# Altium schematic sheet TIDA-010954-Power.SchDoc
size 431 x 279 mm; Date: Not shown in title block; ApprovedBy: Not shown in title block; CheckedBy: Not shown in title block; Author: Not shown in title block; CompanyName: Not shown in title block; Engineer: Not shown in title block; Organization: Not shown in title block; Address1: Not shown in title block; Address2: Not shown in title block; Address3: Not shown in title block; Address4: Not shown in title block; DocumentNumber: 2; Revision: Use project parameter SCH_Rev; SheetNumber: 6; SheetTotal: 9; PageSetup: Record=PageOptions¦CenterHorizontal=True¦CenterVertical=True¦PrintScale=1.00¦XCorrection=1.00¦YCorrection=1.00¦PrintKind=0¦BorderSize=5000000¦LeftOffset=0¦BottomOffset=0¦Orientation=2¦PaperLength=1000¦PaperWidth=1000¦Scale=100¦PaperSource=15¦PrintQuality=600¦MediaType=1¦DitherType=10¦PaperKind=Letter¦PrintScaleMode=1
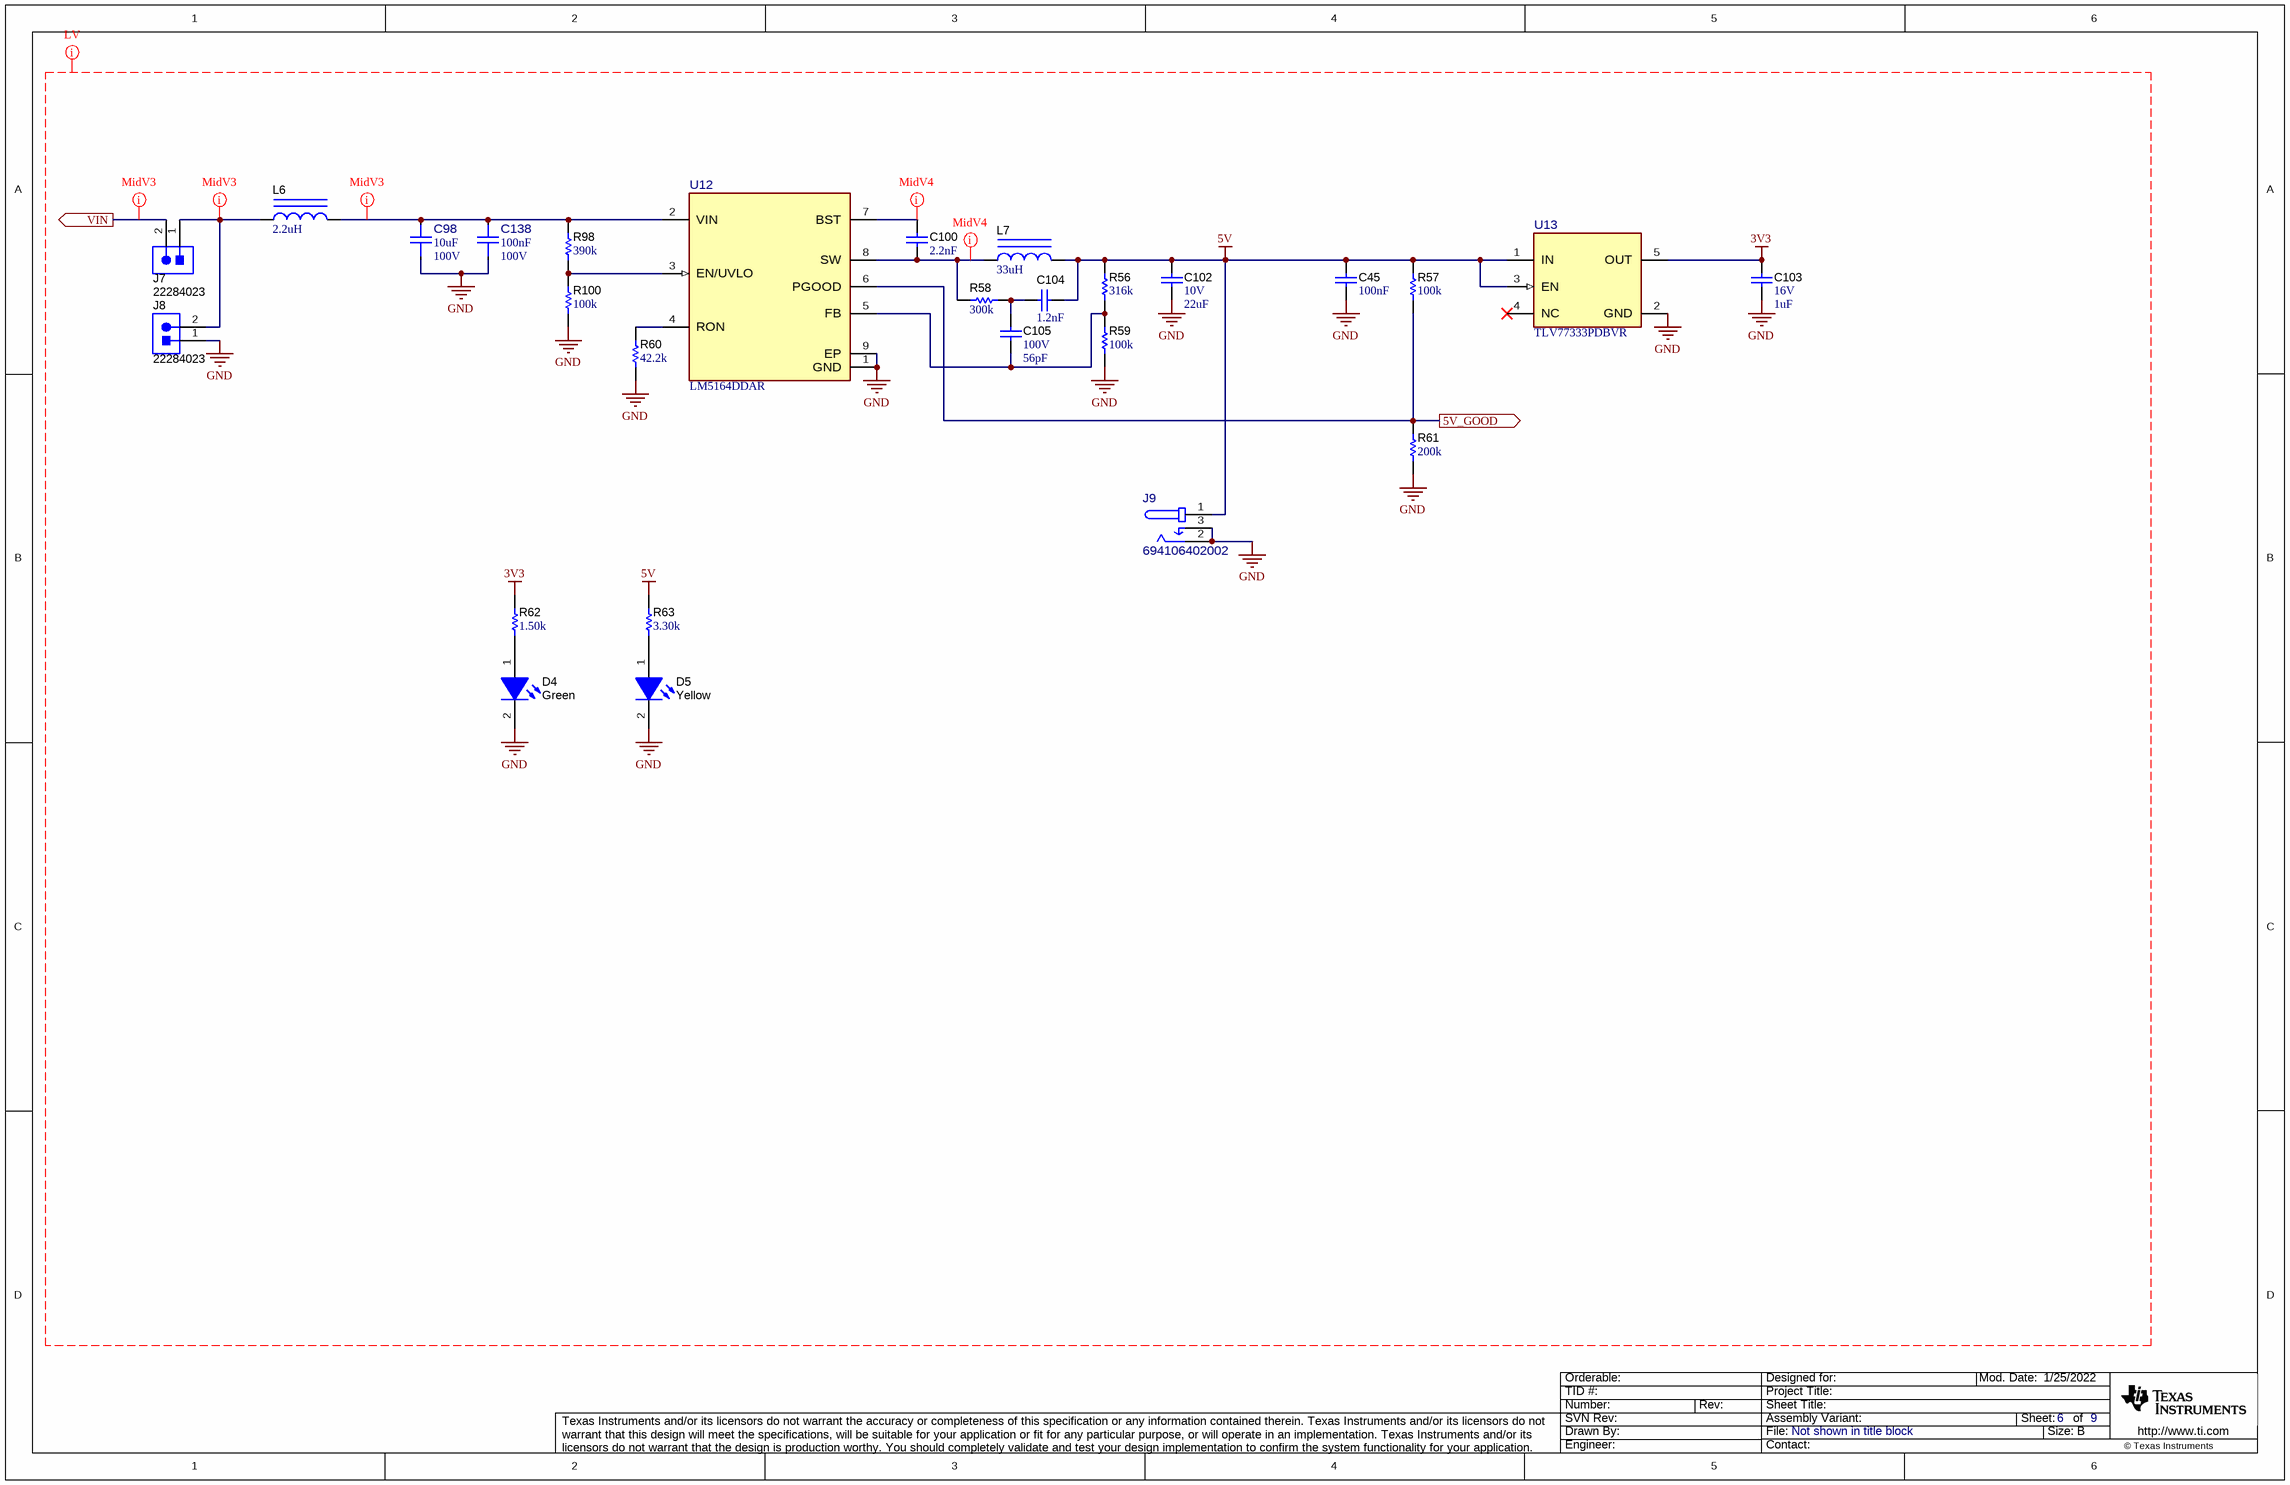
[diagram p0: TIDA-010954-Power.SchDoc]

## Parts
C45  Cap_F: 100nF  [0603]  (hidden comment: CGA3E2X7R1E104K080AA)
C98  ValueDisplayed: 10uF  VDC_V: 100V  [FP-GRM32EC72A106KE05L_1210-MFG]  (hidden comment: GRM32EC72A106KE05L)
C100  Cap_F: 2.2nF  [0603]  (hidden comment: C0603C222K5RAC)
C102  VDC_V: 10V  ValueDisplayed: 22uF  [1206_180]  (hidden comment: GRM31CR71A226KE15L)
C103  VDC_V: 16V  ValueDisplayed: 1uF  [0603]  (hidden comment: GRM185R61C105KE44D)
C104  Cap_F: 1.2nF  [0603]  (hidden comment: GRM188R72A122KA01D)
C105  VDC_V: 100V  ValueDisplayed: 56pF  [0603]  (hidden comment: GRM1885C2A560JA01D)
C138  Cap_F: 100nF  VDC_V: 100V  [FP-GRM188R72A104KA35J_0603-MFG]  (hidden comment: GRM188R72A104KA35J)
D4  value Green  [APT1608_Green]  (hidden comment: APT1608MGC)
D5  value Yellow  [APT1608_Yellow]  (hidden comment: APT1608SYCK)
J7  22284023  [Molex_0022284023]
J8  22284023  [Molex_0022284023]
J9  694106402002  [FP-694106402002_CONN_PWR_10MM7_9MM0-MFG]
L6  ValueDisplayed: 2.2uH  [0805_HV]  (hidden comment: LQM21PN2R2MGS)
L7  ValueDisplayed: 33uH  [SRR1210]  (hidden comment: SRR1210-330M)
R56  ValueDisplayed: 316k  [0603]  (hidden comment: RC0603FR-07316KL)
R57  ValueDisplayed: 100k  [0603]  (hidden comment: RC0603FR-07100KL)
R58  ValueDisplayed: 300k  [0805_HV]  (hidden comment: CRCW0805300KJNEA)
R59  ValueDisplayed: 100k  [0603]  (hidden comment: RC0603FR-07100KL)
R60  ValueDisplayed: 42.2k  [0603]  (hidden comment: RC0603FR-0742K2L)
R61  ValueDisplayed: 200k  [0603]  (hidden comment: RC0603FR-07200KL)
R62  ValueDisplayed: 1.50k  [0603]  (hidden comment: RC0603FR-071K5L)
R63  ValueDisplayed: 3.30k  [0603]  (hidden comment: RC0603FR-073K3L)
R98  ValueDisplayed: 390k  [0805_HV]  (hidden comment: CRCW0805390KJNEA)
R100  ValueDisplayed: 100k  [0603]  (hidden comment: RC0603FR-07100KL)
U12  LM5164DDAR  [DDA0008E-MFG]
U13  TLV77333PDBVR  [DBV0005A-MFG]

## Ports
5V_GOOD (out), VIN (out)

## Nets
3V3: C103.1 R62.2 U13.5(OUT)
5V: C45.2 C102.1 C104.1 J9.1 L7.2 R56.2 R57.2 R63.2 U13.1(IN) U13.3(EN)
GND: C45.1 C98.1 C102.2 C103.2 C138.1 D4.2(K) D5.2(K) J8.1 J9.2 J9.3 R59.1 R60.1 R61.1 R100.1 U12.1(GND) U12.9(EP) U13.2(GND)
5V_GOOD: R57.1 R61.2 U12.6(PGOOD) ; port 5V_GOOD
VIN: J7.2 ; port VIN
NetC98_2: C98.2 C138.2 L6.2 R98.2 U12.2(VIN)
NetC100_1: C100.1 U12.7(BST)
NetC100_2: C100.2 L7.1 R58.1 U12.8(SW)
NetC104_2: C104.2 C105.1 R58.2
NetC105_2: C105.2 R56.1 R59.2 U12.5(FB)
NetD4_1: D4.1(A) R62.1
NetD5_1: D5.1(A) R63.1
NetJ7_1: J7.1 J8.2 L6.1
NetR60_2: R60.2 U12.4(RON)
NetR98_1: R98.1 R100.2 U12.3(EN/UVLO)

Not connected (* = marked no-connect by the designer): U13 4(NC)*

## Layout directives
net class LV: 3V3, 5V, GND
net class MidV3: NetC98_2, NetC100_1, NetC100_2, NetJ7_1, VIN

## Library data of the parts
C45 = CMP-0007077-5: CAP, CERM, 0.1 uF, 25 V, +/- 10%, X7R, AEC-Q200 Grade 1, 0603; Manufacturer: TDK; TaMin_C: -55°C; Polarized: N; SizeAreaWB_mm2: 4.68; Value1: Unknown; U/M: EA; Value: 0.1uF; TaMax_C: 125°C; SizeZ_mm: 1; SizeX_mm: 1.6; SizeY_mm: 0.8; Value2: 25V; SizeArea_mm2: 1.28; AEC Qualified: Y; AEC Category: Q200
C98 = CMP-0087970-1: 10µF ±10% 100V Ceramic Capacitor X7S 1210 (3225 Metric); Manufacturer: Murata; Symbol Name: SYM-GRM32EC72A106KE05L; Tolerance_%: 0.1; AEC Qualified: No; TempCo: 22%; SizeZ_mm: 2.7mm
C100 = CMP-0006897-4: CAP, CERM, 2200 pF, 50 V, +/- 10%, X7R, 0603; Manufacturer: Kemet; TaMin_C: -55°C; Polarized: N; SizeAreaWB_mm2: 4.68; Value1: Unknown; U/M: EA; Value: 2200pF; TaMax_C: 125°C; SizeZ_mm: 1; SizeX_mm: 1.6; SizeY_mm: 0.8; Value2: 50V; SizeArea_mm2: 1.28; AEC Category: Q200
C102 = CMP-0008959-2: CAP, CERM, 22 uF, 10 V, +/- 10%, X7R, 1206; Manufacturer: MuRata; TaMin_C: -55°C; Polarized: N; SizeAreaWB_mm2: 10.92; Value1: Unknown; U/M: EA; Value: 22uF; TaMax_C: 125°C; SizeZ_mm: 1.8; SizeX_mm: 3.2; SizeY_mm: 1.6; Cap_Case: 1206; SizeArea_mm2: 5.12; Cap_F: 22µF; AEC Category: Q200
C103 = CMP-0007157-5: CAP, CERM, 1 uF, 16 V, +/- 10%, X5R, 0603; Manufacturer: MuRata; TaMin_C: -55°C; Polarized: N; SizeAreaWB_mm2: 4.68; Value1: Unknown; U/M: EA; Value: 1uF; TaMax_C: 85°C; SizeZ_mm: 1; SizeX_mm: 1.6; SizeY_mm: 0.8; SizeArea_mm2: 1.28; Cap_F: 1µF; AEC Category: Q200
C104 = CMP-0007471-5: CAP, CERM, 1200 pF, 100 V, +/- 10%, X7R, 0603; Manufacturer: MuRata; TaMin_C: -55°C; Polarized: N; SizeAreaWB_mm2: 4.68; Value1: Unknown; U/M: EA; Value: 1200pF; TaMax_C: 125°C; SizeZ_mm: 1; SizeX_mm: 1.6; SizeY_mm: 0.8; Value2: 100V; SizeArea_mm2: 1.28; AEC Category: Q200
C105 = CMP-0007275-4: CAP, CERM, 56 pF, 100 V, +/- 5%, C0G/NP0, 0603; Manufacturer: MuRata; TaMin_C: -55°C; Polarized: N; SizeAreaWB_mm2: 4.68; Value1: Unknown; U/M: EA; Value: 56pF; TaMax_C: 125°C; SizeZ_mm: 1; SizeX_mm: 1.6; SizeY_mm: 0.8; SizeArea_mm2: 1.28; AEC Category: Q200
C138 = CMP-0122713-1: Chip Multilayer Ceramic Capacitors for General Purpose, 0603, 0.10uF, X7R, 15%, 10%, 100V; Manufacturer: Murata; AEC Qualified: No; SizeZ_mm: 0.9mm; Value: 100nF
D4 = CMP-0002943-3: LED, Green, SMD; Manufacturer: Kingbright; Value2: 2.1V; Vr_V: 5V; Ir_A: 10µA; Io_A: 20mA; Angle: 120; Tjmax_C: 85°C; Value1: W
D5 = CMP-0002944-3: LED, Yellow, SMD; Manufacturer: Kingbright; Value2: 2.5V; Ir_A: 10µA; Tjmax_C: 85°C; Value1: W; Io_A: 20mA; Vr_V: 5V; Angle: 120
J7 J8 = CMP-0055333-1: Header, 2.54mm, 2x1, Tin, TH; Manufacturer: Molex; CNHeader: TRUE; Current_A: 4A; Shrouded: N; Gender: Male; Voltage_V: 250V; Row_Count: 1; Pitch_mm: 2.54; CT: FALSE; Cert_UL: Y
J9 = CMP-0040211-1: Power Barrel Connector Jack 2.10mm ID (0.083"), 5.50mm OD (0.217") Through Hole; Manufacturer: Wurth Electronics; ContactFinish: Gold; Current_A: 3A; Voltage_V: 30V; AEC Qualified: No; Conn Gender: Female; Conn Orientation: Vertical; SizeZ_mm: 14.3mm
L6 = CMP-0058745-1: Inductor, Multilayer, Ferrite, 2.2 uH, 0.95 A, 0.18 ohm, SMD; Manufacturer: MuRata; Green_Lifecycle: Active; SizeAreaWB_mm2: 6.75; DCR_ohm: 1.8d; Green_REACh: Passed; Value: 2.2uH; Imax_A: 9.5dA; SizeZ_mm: 1.45; SizeX_mm: 2; SizeY_mm: 1.25; Value2: 0.95A; SizeArea_mm2: 2.5; Ind_H: 2.2µH; AEC Category: Q200
L7 = CMP-0057850-2: Inductor, Drum Core, Ferrite, 33 uH, 3.7 A, 0.052 ohm, SMD; Manufacturer: Bourns; Isat: 3.7A @ 20% inductance drop; Irms: 4.4A @ 40C rise; Green_Lifecycle: Active; SizeAreaWB_mm2: 196; DCR_ohm: 0.052; Green_REACh: Passed; Value: 33uH; Imax_A: 3.7A; SizeZ_mm: 10; SizeX_mm: 12; SizeArea_mm2: 144; Ind_H: 33µH; AEC Category: Q200
R56 = CMP-0023024-4: RES, 316 k, 1%, 0.1 W, 0603; Manufacturer: Yageo; Power_W: 100mW; TempCo: 100 ppm/C; Value: 316k; EIA_Code: E96; SizeX_mm: 1.6; SizeY_mm: 0.8; SizeZ_mm: 1; Value2: 0.1W; SizeArea_mm2: 1.28; AEC Qualified: N; VDC_V: 75V; AEC Category: Q200; SizeAreaWB_mm2: 4.68
R57 R59 R100 = CMP-0022735-5: RES, 100 k, 1%, 0.1 W, 0603; Manufacturer: Yageo; Power_W: 100mW; TempCo: 100 ppm/C; Value: 100k; EIA_Code: E96; SizeX_mm: 1.6; SizeY_mm: 0.8; SizeZ_mm: 1; Value2: 0.1W; SizeArea_mm2: 1.28; AEC Qualified: N; VDC_V: 75V; AEC Category: Q200; SizeAreaWB_mm2: 4.68
R58 = CMP-0020522-3: RES, 300 k, 5%, 0.125 W, AEC-Q200 Grade 0, 0805; Manufacturer: Vishay-Dale; Power_W: 125mW; TempCo: 200 ppm/C; Value: 300k; EIA_Code: E24; SizeX_mm: 2; SizeY_mm: 1.25; SizeZ_mm: 1.45; Value2: 0.125W; SizeArea_mm2: 2.5; AEC Qualified: Y; VDC_V: 150V; AEC Category: Q200; AEC Grade: 0
R60 = CMP-0023106-5: RES, 42.2 k, 1%, 0.1 W, 0603; Manufacturer: Yageo; Power_W: 100mW; TempCo: 100 ppm/C; Value_Code: 42k2; Value: 42.2k; EIA_Code: E96; SizeX_mm: 1.6; SizeY_mm: 0.8; SizeZ_mm: 1; Value2: 0.1W; SizeArea_mm2: 1.28; AEC Qualified: N; VDC_V: 75V; AEC Category: Q200; SizeAreaWB_mm2: 4.68
R61 = CMP-0022901-4: RES, 200 k, 1%, 0.1 W, 0603; Manufacturer: Yageo; Power_W: 100mW; TempCo: 100 ppm/C; Value: 200k; EIA_Code: E96; SizeX_mm: 1.6; SizeY_mm: 0.8; SizeZ_mm: 1; Value2: 0.1W; AEC Qualified: N; VDC_V: 75V; AEC Category: Q200; SizeArea_mm2: 1.28; SizeAreaWB_mm2: 4.68
R62 = CMP-0022883-5: RES, 1.50 k, 1%, 0.1 W, 0603; Manufacturer: Yageo; Power_W: 100mW; TempCo: 100 ppm/C; Value_Code: 1k50; Value: 1.50k; EIA_Code: E96; Res_ohm: 1.5k; SizeX_mm: 1.6; SizeY_mm: 0.8; SizeZ_mm: 1; Value2: 0.1W; SizeArea_mm2: 1.28; AEC Qualified: N; VDC_V: 75V; AEC Category: Q200; SizeAreaWB_mm2: 4.68
R63 = CMP-0023081-5: RES, 3.30 k, 1%, 0.1 W, 0603; Manufacturer: Yageo; Power_W: 100mW; TempCo: 100 ppm/C; Value_Code: 3k30; Value: 3.30k; Res_ohm: 3.3k; SizeX_mm: 1.6; SizeY_mm: 0.8; SizeZ_mm: 1; Value2: 0.1W; SizeArea_mm2: 1.28; AEC Qualified: N; VDC_V: 75V; AEC Category: Q200; SizeAreaWB_mm2: 4.68
R98 = CMP-0020534-3: RES, 390 k, 5%, 0.125 W, AEC-Q200 Grade 0, 0805; Manufacturer: Vishay-Dale; Power_W: 125mW; TempCo: 200 ppm/C; Value: 390k; EIA_Code: E24; SizeX_mm: 2; SizeY_mm: 1.25; SizeZ_mm: 1.45; Value2: 0.125W; SizeArea_mm2: 2.5; AEC Qualified: Y; VDC_V: 150V; AEC Category: Q200; AEC Grade: 0
U12 = CMP-0089262-2: Manufacturer: Texas Instruments; AEC Qualified: No; Standoff Height: 0mm; AEC Category: Q200; Max Duty Cycle: 99%; Nominal Supply Current: 600uA; Max Supply Voltage: 100V; Number Of Outputs: 1; Switching Frequency: 1MHz; Output Type: AdjustableProgrammable; Switching Topology: Buck; Min Supply Voltage: 6V; CompType: IC; Output Voltage: 1.2-90V; TJmax_C: +150°C
U13 = CMP-0033468-1: 300-mA, Small-Size, High-PSRR LDO; Manufacturer: Texas Instruments; SizeZ_mm: 1.45mm; AEC Qualified: No; Accuracy Percentage: 1%; Dropout Voltage: 200mV; Max Supply Voltage: 5.5V; Min Supply Voltage: 3.8V; Nominal Supply Current: 80uA; Number Of Outputs: 1; Output Type: Fixed; Output Voltage: 3.3V; Standoff Height: 0mm; TJmax_C: +85°C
